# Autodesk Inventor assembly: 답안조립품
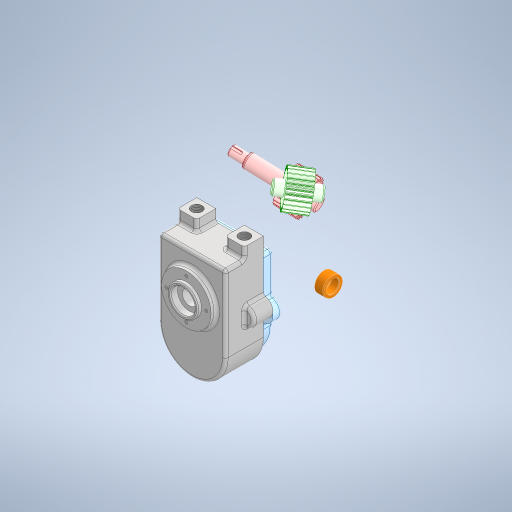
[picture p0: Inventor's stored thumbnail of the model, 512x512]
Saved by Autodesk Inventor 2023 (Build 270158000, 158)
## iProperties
Created: 2024-03
Part Number: 답안조립품
Document SubType Name: Assembly
Designer: asung
Author: asung
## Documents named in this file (6)
- C:\Users\asung\Desktop\740304V1008\답안조립품.iam
- C:\Users\asung\Desktop\740304V1008\본체.ipt
- C:\Users\asung\Desktop\740304V1008\오일레스 부시.ipt
- C:\Users\asung\Desktop\740304V1008\구동기어.ipt
- C:\Users\asung\Desktop\740304V1008\스퍼기어.ipt
- C:\Users\asung\Desktop\740304V1008\커버.ipt
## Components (1 placed, 1 different names)
1. 구동기어:1
